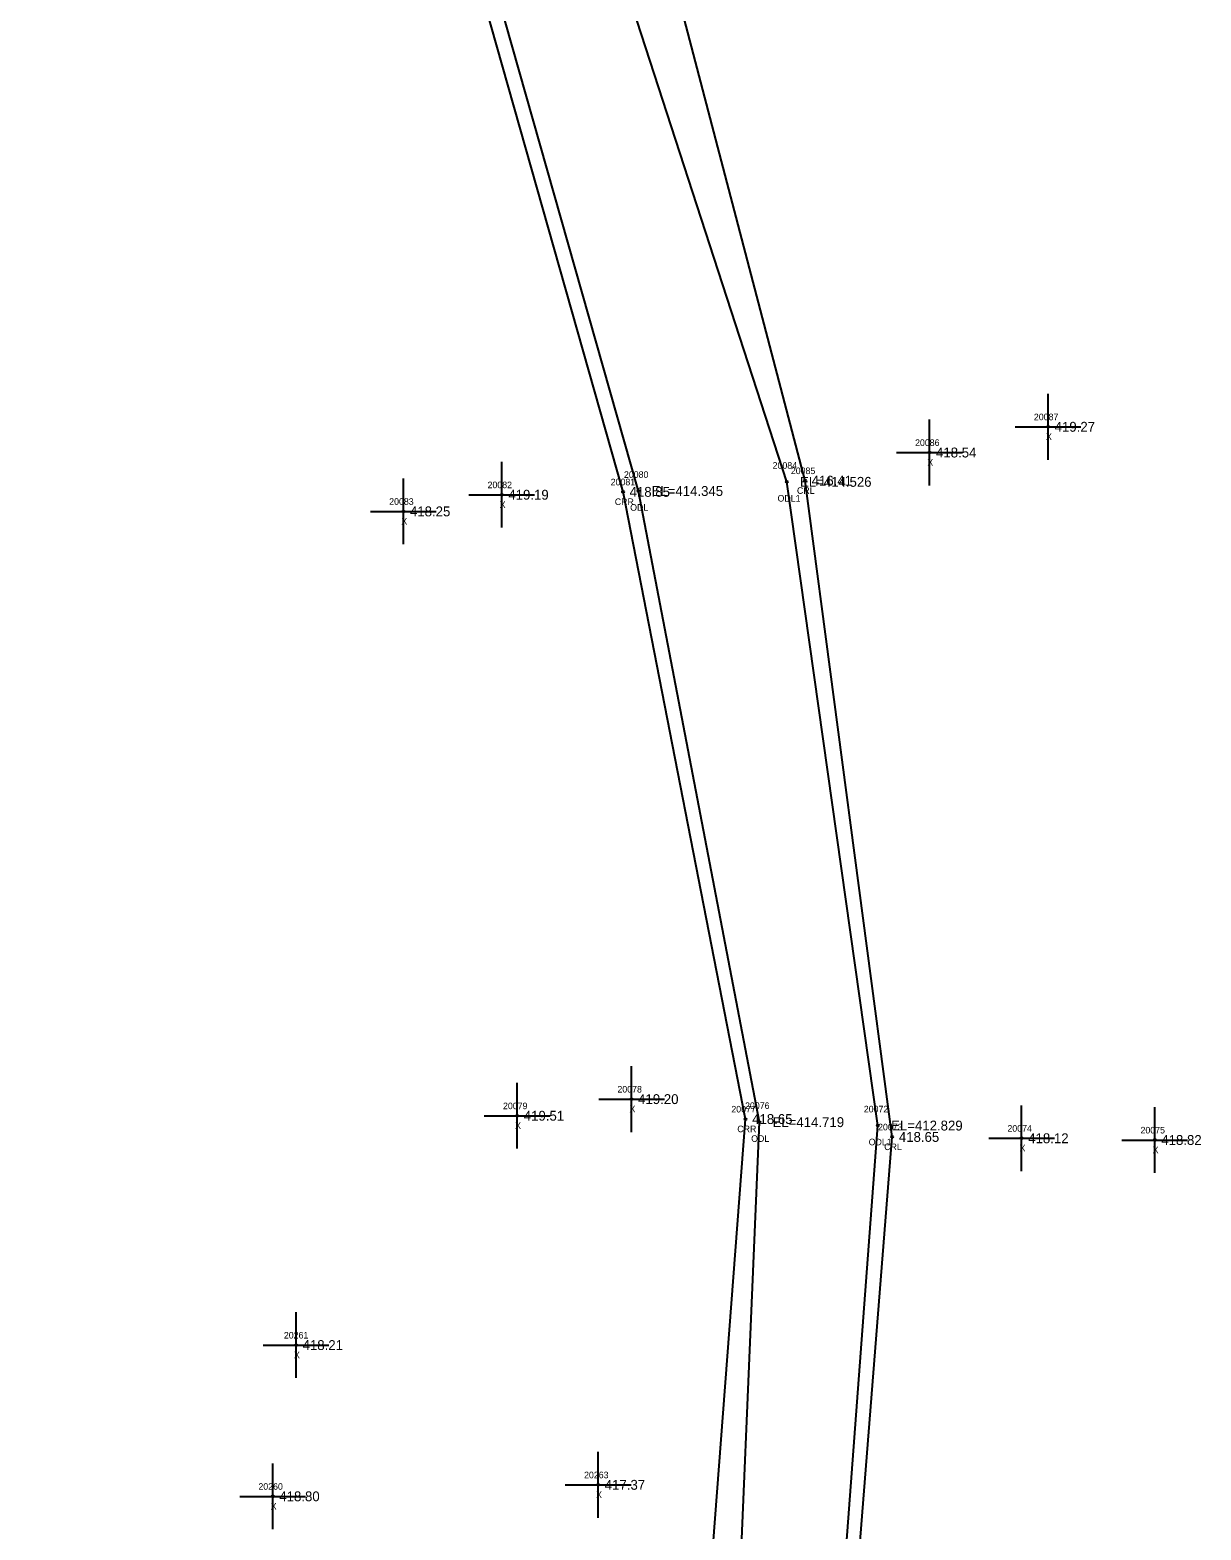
# Model space of a CAD drawing. Extents: x 1613184 to 1614731, y 770859 to 771868.
# Drawn here: x 1613812.2 to 1613990.2, y 771395.6 to 771623.6 of the extents above; entities that cross this region are included whole.
import ezdxf

# ---------------------------------------------------------------- set-up
doc = ezdxf.new("R2010")
doc.units = 0
for name, color, linetype in [('RD_EX_H2O', 7, 'Continuous'), ('RD_EX_H2O_txCode', 7, 'Continuous'), ('RD_EX_Misc', 7, 'Continuous'), ('RD_EX_Misc_txCode', 7, 'Continuous'), ('RD_EX_TX_H2O_ELEV', 7, 'Continuous'), ('RD_EX_TX_Misc_ELEV', 7, 'Continuous'), ('RD_SMD_Locator', 7, 'Continuous')]:
    doc.layers.add(name, color=color, linetype=linetype)

msp = doc.modelspace()

# ---------------------------------------------------------------- linework, layer by layer
at = {"layer": 'RD_EX_H2O'}
for points in [[(1613935.44, 771356.77), (1613943.27, 771455.38), (1613930.01, 771555.13), (1613904.31, 771653.52), (1613890.61, 771671.71), (1613879.59, 771707.51), (1613867.74, 771752.9), (1613852.65, 771773.53), (1613849.08, 771793.99), (1613835.96, 771848.52)], [(1613917.33, 771358.45), (1613914.84, 771377.38), (1613920.97, 771458.1), (1613902.34, 771553.43), (1613877.06, 771642.7), (1613869.36, 771660.93), (1613852.51, 771699.26), (1613841.87, 771743.26), (1613831.92, 771763.8), (1613826.06, 771789.11), (1613812.2, 771844.94)], [(1613918.86, 771358.4), (1613923.07, 771457.63), (1613904.68, 771553.56), (1613879.07, 771643.9), (1613870.63, 771662.43), (1613861.21, 771701.73), (1613845.61, 771745.37), (1613835.05, 771764.94), (1613829.4, 771789.26), (1613813.84, 771845.46)], [(1613933.56, 771356.85), (1613941.09, 771457.11), (1613927.24, 771554.95), (1613896.69, 771649.06), (1613889.05, 771670.7), (1613877.65, 771707.88), (1613864.46, 771751.42), (1613851.59, 771772.54), (1613846.49, 771794.39), (1613833.03, 771846.8)]]:
    msp.add_lwpolyline(points, dxfattribs=at)
at = {"layer": 'RD_EX_Misc'}
for p, q in [((1613966.95, 771558.32), (1613966.95, 771568.32)), ((1613948.92, 771554.41), (1613948.92, 771564.41)), ((1613961.95, 771563.32), (1613971.95, 771563.32)), ((1613883.91, 771547.99), (1613883.91, 771557.99)), ((1613943.92, 771559.41), (1613953.92, 771559.41)), ((1613868.96, 771545.46), (1613868.96, 771555.46)), ((1613878.91, 771552.99), (1613888.91, 771552.99)), ((1613863.96, 771550.46), (1613873.96, 771550.46)), ((1613903.64, 771456.13), (1613903.64, 771466.13)), ((1613886.26, 771453.6), (1613886.26, 771463.6)), ((1613898.64, 771461.13), (1613908.64, 771461.13)), ((1613962.93, 771450.18), (1613962.93, 771460.18)), ((1613983.16, 771449.91), (1613983.16, 771459.91)), ((1613881.26, 771458.6), (1613891.26, 771458.6)), ((1613957.93, 771455.18), (1613967.93, 771455.18)), ((1613978.16, 771454.91), (1613988.16, 771454.91)), ((1613852.64, 771418.74), (1613852.64, 771428.74)), ((1613847.64, 771423.74), (1613857.64, 771423.74)), ((1613898.57, 771397.5), (1613898.57, 771407.5)), ((1613849.1, 771395.75), (1613849.1, 771405.75)), ((1613893.57, 771402.5), (1613903.57, 771402.5)), ((1613844.1, 771400.75), (1613854.1, 771400.75))]:
    msp.add_line(p, q, dxfattribs=at)
at = {"layer": 'RD_SMD_Locator'}
for centre in [(1613966.95, 771563.32), (1613948.92, 771559.41), (1613927.24, 771554.95), (1613930.01, 771555.13), (1613883.91, 771552.99), (1613902.34, 771553.43), (1613904.68, 771553.56), (1613868.96, 771550.46), (1613903.64, 771461.13), (1613886.26, 771458.6), (1613920.97, 771458.1), (1613923.07, 771457.63), (1613941.09, 771457.11), (1613943.27, 771455.38), (1613962.93, 771455.18), (1613983.16, 771454.91), (1613852.64, 771423.74), (1613898.57, 771402.5), (1613849.1, 771400.75)]:
    msp.add_circle(centre, 0.15, dxfattribs=at)

# ---------------------------------------------------------------- texts
at = {"layer": 'RD_EX_H2O_txCode'}
for s, p in [('20084', (1613925.08, 771556.95)), ('20081', (1613900.47, 771554.43)), ('20080', (1613902.48, 771555.56)), ('20085', (1613927.85, 771556.13)), ('ODL1', (1613925.83, 771551.95)), ('CRL', (1613928.78, 771553.13)), ('CRR', (1613901.09, 771551.43)), ('ODL', (1613903.43, 771550.56)), ('20077', (1613918.81, 771459.1)), ('20076', (1613920.89, 771459.63)), ('20072', (1613938.94, 771459.11)), ('CRR', (1613919.71, 771456.1)), ('20073', (1613941.11, 771456.38)), ('ODL', (1613921.82, 771454.63)), ('ODL1', (1613939.68, 771454.11)), ('CRL', (1613942.04, 771453.38))]:
    msp.add_text(s, height=1, dxfattribs=at).set_placement(p)
at = {"layer": 'RD_EX_Misc_txCode'}
for s, p in [('20087', (1613964.79, 771564.32)), ('X', (1613966.63, 771561.32)), ('20086', (1613946.73, 771560.41)), ('X', (1613948.6, 771557.41)), ('20082', (1613881.75, 771553.99)), ('20083', (1613866.8, 771551.46)), ('X', (1613883.59, 771550.99)), ('X', (1613868.65, 771548.46)), ('20078', (1613901.49, 771462.13)), ('20079', (1613884.1, 771459.6)), ('X', (1613903.33, 771459.13)), ('X', (1613885.94, 771456.6)), ('20074', (1613960.77, 771456.18)), ('20075', (1613981, 771455.91)), ('X', (1613962.61, 771453.18)), ('X', (1613982.84, 771452.91)), ('20261', (1613850.79, 771424.74)), ('X', (1613852.33, 771421.74)), ('20263', (1613896.42, 771403.5)), ('20260', (1613846.92, 771401.75)), ('X', (1613898.25, 771400.5)), ('X', (1613848.79, 771398.75))]:
    msp.add_text(s, height=1, dxfattribs=at).set_placement(p)
at = {"layer": 'RD_EX_TX_H2O_ELEV'}
for s, p in [('EL=414.526', (1613929.24, 771554.2)), ('416.41', (1613931.01, 771554.38)), ('418.85', (1613903.34, 771552.68)), ('EL=414.345', (1613906.68, 771552.81)), ('418.65', (1613921.97, 771457.35)), ('EL=414.719', (1613925.07, 771456.88)), ('EL=412.829', (1613943.09, 771456.36)), ('418.65', (1613944.27, 771454.63))]:
    msp.add_text(s, height=1.5, dxfattribs=at).set_placement(p)
at = {"layer": 'RD_EX_TX_Misc_ELEV'}
for s, p in [('419.27', (1613967.95, 771562.57)), ('418.54', (1613949.92, 771558.66)), ('419.19', (1613884.91, 771552.24)), ('418.25', (1613869.96, 771549.71)), ('419.20', (1613904.64, 771460.38)), ('419.51', (1613887.26, 771457.85)), ('418.12', (1613963.93, 771454.43)), ('418.82', (1613984.16, 771454.16)), ('418.21', (1613853.64, 771422.99)), ('417.37', (1613899.57, 771401.75)), ('418.80', (1613850.1, 771400))]:
    msp.add_text(s, height=1.5, dxfattribs=at).set_placement(p)

doc.saveas('drawing.dxf')
